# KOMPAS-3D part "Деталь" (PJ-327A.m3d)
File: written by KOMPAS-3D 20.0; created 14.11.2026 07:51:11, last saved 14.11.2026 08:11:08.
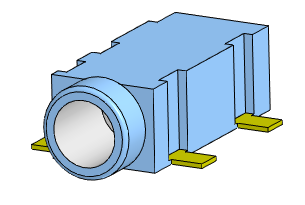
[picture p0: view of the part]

Document properties: Полное имя файла: D:\myProjects\Progect_esp32\box_compas\разъемы\PJ-327A.m3d

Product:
- Part/product: Деталь
    Масса: 0.00239431
  - Body: Тело 1
      Масса: 0.00258777

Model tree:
1. Эскиз:1
2. Элемент выдавливания:1
     Расстояние 1 = 12.2
3. Эскиз:2  (with: Элемент выдавливания:1)
4. Элемент выдавливания:2
     Расстояние 1 = 2
5. Эскиз:3  (with: Элемент выдавливания:2)
6. Элемент выдавливания:3
     Расстояние 2 = 5
7. Скругление:1  (with: Элемент выдавливания:2)
     Радиус = 0.25
8. Эскиз:4  (with: Элемент выдавливания:1, Скругление:1)
9. Элемент выдавливания:4
     Расстояние 2 = 0.25
10. Эскиз:5  (with: Элемент выдавливания:1, Элемент выдавливания:2)
11. Элемент выдавливания:5
     Расстояние 1 = 0.8
12. Скругление:2  (with: Элемент выдавливания:5)
     Радиус = 0.25
13. Эскиз:6  (with: Элемент выдавливания:1, Элемент выдавливания:4)
14. Элемент выдавливания:6
     Расстояние 2 = 4.25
